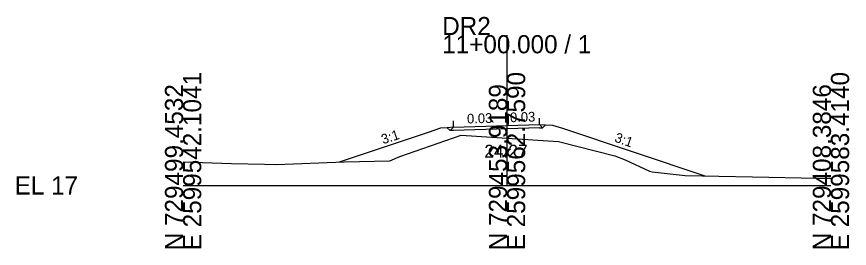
# Model space of a CAD drawing. Extents: x -26 to 1162, y -10 to 9515.
# Drawn here: x -25.7 to 102.8, y 4990.3 to 5026 of the extents above; entities that cross this region are included whole.
import ezdxf

# ---------------------------------------------------------------- set-up
doc = ezdxf.new("R2010")
doc.units = 0
for name, color, linetype in [('Exist Cross Section Cell', 7, 'Continuous'), ('Exist XS Center Line Elevation Label', 7, 'Continuous'), ('Exist XS Ground Line', 7, 'Continuous'), ('Prop XS Dump Level', 7, 'Continuous'), ('Prop XS EOT Tick Mark', 7, 'Continuous'), ('Prop XS Finish Grade', 7, 'Continuous'), ('Prop XS Finish Grade Earthwork', 7, 'Continuous'), ('Prop XS Finish Grade Pavement', 7, 'Continuous'), ('Prop XS Pvmt Edge Slope', 7, 'Continuous'), ('Prop XS SE Text', 7, 'Continuous'), ('Prop XS Side Slope Text', 7, 'Continuous'), ('Prop XS Subgrade Earthwork', 7, 'Continuous')]:
    doc.layers.add(name, color=color, linetype=linetype)

msp = doc.modelspace()

# ---------------------------------------------------------------- linework, layer by layer
at = {"layer": 'Exist Cross Section Cell'}
for p, q in [((50, 5000), (50, 5023.16)), ((0, 5000), (50, 5000)), ((50, 5000), (100, 5000))]:
    msp.add_line(p, q, dxfattribs=at)
at = {"layer": 'Exist XS Ground Line'}
msp.add_lwpolyline([(0, 5003.61), (7.46, 5003.4), (12.55, 5003.27), (14.42, 5003.22), (24.86, 5003.62), (31.91, 5003.8), (33.47, 5004.44), (42.9, 5007.72), (50, 5007.27), (57.97, 5006.77), (66.62, 5004.55), (68.25, 5003.92), (72.01, 5002.19), (72.41, 5002.07), (77.5, 5001.53), (87.87, 5001.34), (97.91, 5001.1), (100, 5001.1)], dxfattribs=at)
at = {"layer": 'Prop XS Dump Level'}
for p, q in [((41.72, 5008.96), (50, 5009.22)), ((50, 5009.22), (55, 5009.37))]:
    msp.add_line(p, q, dxfattribs=at)
at = {"layer": 'Prop XS EOT Tick Mark'}
for p, q in [((55, 5009.37), (55, 5010.37)), ((41.72, 5008.96), (41.72, 5009.96))]:
    msp.add_line(p, q, dxfattribs=at)
at = {"layer": 'Prop XS Finish Grade'}
for p, q in [((41.72, 5008.96), (40.76, 5008.88)), ((55, 5009.37), (55.95, 5009.34))]:
    msp.add_line(p, q, dxfattribs=at)
at = {"layer": 'Prop XS Finish Grade Earthwork'}
for p, q in [((55.95, 5009.34), (57, 5009.31)), ((57, 5009.31), (58.55, 5008.8)), ((37.85, 5008.18), (24.09, 5003.59)), ((39.72, 5008.8), (37.85, 5008.18)), ((40.76, 5008.88), (39.72, 5008.8)), ((58.55, 5008.8), (80.52, 5001.47))]:
    msp.add_line(p, q, dxfattribs=at)
at = {"layer": 'Prop XS Finish Grade Pavement'}
for p, q in [((41.72, 5008.96), (50, 5009.22)), ((50, 5009.22), (55, 5009.37))]:
    msp.add_line(p, q, dxfattribs=at)
at = {"layer": 'Prop XS Pvmt Edge Slope'}
for p, q in [((41.72, 5008.96), (41.2, 5008.45)), ((55, 5009.37), (55.49, 5008.89)), ((55.49, 5008.89), (55.95, 5009.34)), ((41.2, 5008.45), (40.76, 5008.88))]:
    msp.add_line(p, q, dxfattribs=at)
at = {"layer": 'Prop XS Subgrade Earthwork'}
for p, q in [((55.49, 5008.89), (55.95, 5009.34)), ((41.2, 5008.45), (40.76, 5008.88)), ((41.72, 5008.46), (41.2, 5008.45)), ((50, 5008.72), (41.72, 5008.46)), ((55, 5008.87), (50, 5008.72)), ((55, 5008.87), (55.49, 5008.89))]:
    msp.add_line(p, q, dxfattribs=at)

# ---------------------------------------------------------------- texts
at = {"layer": 'Exist Cross Section Cell'}
for s, p in [('DR2', (40, 5023.16)), ('11+00.000 / 1', (40, 5020.36)), ('EL 17', (-26, 4998.6))]:
    msp.add_text(s, height=2.8, dxfattribs=at).set_placement(p)
for s, p in [('E 2599542.1041', (2.8, 4990)), ('E 2599562.7590', (52.8, 4990)), ('E 2599583.4140', (102.8, 4990)), ('N 729499.4532', (0, 4990)), ('N 729453.9189', (50, 4990)), ('N 729408.3846', (100, 4990))]:
    msp.add_text(s, height=2.8, rotation=90, dxfattribs=at).set_placement(p)
at = {"layer": 'Exist XS Center Line Elevation Label'}
msp.add_text('24.27', height=2, dxfattribs=at).set_placement((46.49, 5004.27))
at = {"layer": 'Prop XS Dump Level'}
for p in [(57, 5009.27), (39.72, 5008.76)]:
    msp.add_text('Case1', height=0.04, dxfattribs=at).set_placement(p)
at = {"layer": 'Prop XS SE Text'}
for p in [(43.84, 5009.53), (50.48, 5009.73)]:
    msp.add_text('0.03', height=1.5, rotation=1.7644, dxfattribs=at).set_placement(p)
at = {"layer": 'Prop XS Side Slope Text'}
for rotation, p in [(18.1082, (30.87, 5006.33)), (340.3993, (66.49, 5006.78))]:
    msp.add_text('3:1', height=1.5, rotation=rotation, dxfattribs=at).set_placement(p)

doc.saveas('drawing.dxf')
